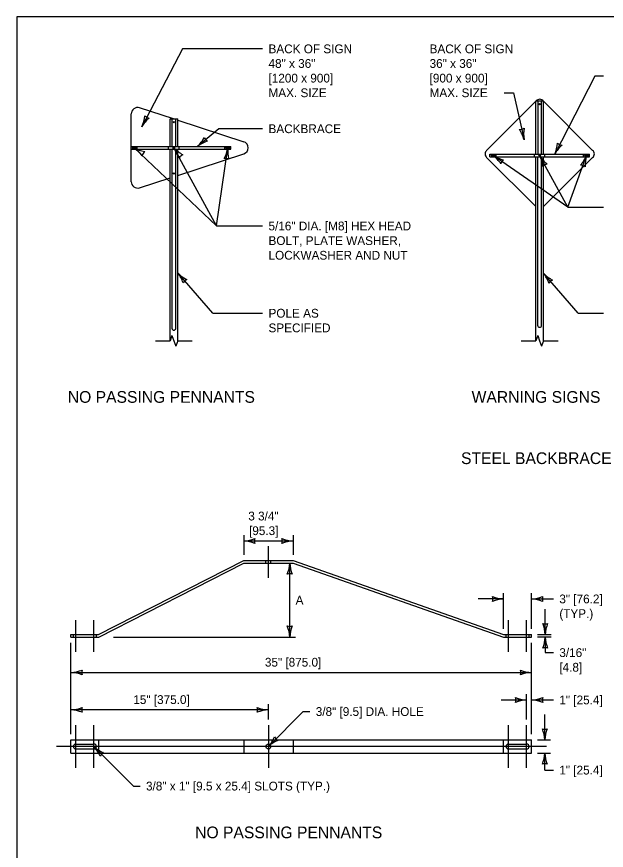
# Model space of a CAD drawing. Extents: x 49991.4 to 50021, y 49987.6 to 50011.4.
# Drawn here: x 50000.34 to 50004.36, y 50005.57 to 50011.26 of the extents above; entities that cross this region are included whole.
import ezdxf

# ---------------------------------------------------------------- set-up
doc = ezdxf.new("R2010")
doc.units = 0
for name, color, linetype in [('Level 1', 7, 'Continuous'), ('Level 2', 7, 'Continuous'), ('Level 3', 7, 'Continuous'), ('Level 4', 7, 'Continuous'), ('Level 5', 7, 'Continuous'), ('Level 6', 7, 'Continuous')]:
    doc.layers.add(name, color=color, linetype=linetype)

msp = doc.modelspace()

# ---------------------------------------------------------------- linework, layer by layer
at = {"layer": 'Level 1'}
for p, q in [((50003.8814, 50010.6855), (50003.5454, 50010.3494)), ((50003.8814, 50010.6878), (50003.9332, 50010.6878)), ((50003.8814, 50010.324), (50003.8814, 50010.6878)), ((50003.8941, 50010.6878), (50003.8941, 50010.324)), ((50003.9211, 50010.324), (50003.9211, 50010.6878)), ((50003.9332, 50010.324), (50003.9332, 50010.6878)), ((50003.9332, 50010.6855), (50004.2692, 50010.3494)), ((50001.1177, 50010.1354), (50001.1177, 50010.5983)), ((50001.406, 50010.5648), (50001.1749, 50010.6398)), ((50001.3834, 50010.5648), (50001.4352, 50010.5648)), ((50001.3834, 50010.3765), (50001.3834, 50010.5648)), ((50001.3962, 50010.5648), (50001.3962, 50010.3765)), ((50001.4232, 50010.3765), (50001.4232, 50010.5648)), ((50001.4352, 50010.3765), (50001.4352, 50010.5648)), ((50001.4352, 50010.5553), (50001.8871, 50010.4085)), ((50001.1177, 50010.3765), (50001.798, 50010.3765)), ((50001.1276, 50010.3697), (50001.149, 50010.3697)), ((50001.1276, 50010.3639), (50001.149, 50010.3639)), ((50001.159, 50010.3571), (50001.159, 50010.3765)), ((50001.3734, 50010.3571), (50001.3734, 50010.3765)), ((50001.4452, 50010.3571), (50001.4452, 50010.3765)), ((50001.7567, 50010.3571), (50001.7567, 50010.3765)), ((50001.7667, 50010.3699), (50001.7881, 50010.3699)), ((50001.7667, 50010.364), (50001.7881, 50010.364)), ((50001.798, 50010.3571), (50001.798, 50010.3765)), ((50001.1177, 50010.3571), (50001.798, 50010.3571)), ((50001.3834, 50009.0483), (50001.3834, 50010.3571)), ((50001.3958, 50010.3571), (50001.3958, 50009.1339)), ((50001.4228, 50009.1339), (50001.4228, 50010.3571)), ((50001.4352, 50009.0483), (50001.4352, 50010.3571)), ((50001.4352, 50010.1783), (50001.8872, 50010.325)), ((50003.5681, 50010.324), (50004.2485, 50010.324)), ((50003.5681, 50010.3045), (50003.5681, 50010.324)), ((50003.5681, 50010.3045), (50004.2485, 50010.3045)), ((50003.5784, 50010.3173), (50003.5998, 50010.3173)), ((50003.5784, 50010.3115), (50003.5998, 50010.3115)), ((50003.6094, 50010.3045), (50003.6094, 50010.324)), ((50003.8714, 50010.3045), (50003.8714, 50010.324)), ((50003.8814, 50009.0483), (50003.8814, 50010.3045)), ((50003.8938, 50010.3045), (50003.8938, 50009.154)), ((50003.9208, 50009.154), (50003.9208, 50010.3045)), ((50003.9332, 50009.0483), (50003.9332, 50010.3045)), ((50003.9432, 50010.3045), (50003.9432, 50010.324)), ((50004.2072, 50010.3045), (50004.2072, 50010.324)), ((50004.2173, 50010.3173), (50004.2387, 50010.3173)), ((50004.2173, 50010.3115), (50004.2387, 50010.3115)), ((50004.2485, 50010.3045), (50004.2485, 50010.324)), ((50003.8814, 50009.9648), (50003.5454, 50010.3009)), ((50003.9332, 50009.9648), (50004.2692, 50010.3009)), ((50001.1749, 50010.0938), (50001.3834, 50010.1615)), ((50000.8934, 50007.0404), (50001.8861, 50007.546)), ((50000.8971, 50007.0236), (50001.8861, 50007.5292)), ((50001.8861, 50007.546), (50002.2231, 50007.546)), ((50001.8861, 50007.5292), (50002.2231, 50007.5292)), ((50002.2231, 50007.546), (50003.6609, 50007.0404)), ((50002.2231, 50007.5292), (50003.6609, 50007.0236)), ((50000.7061, 50007.0236), (50000.7061, 50007.0404)), ((50000.7061, 50007.0404), (50000.8934, 50007.0404)), ((50000.7061, 50007.0236), (50000.8971, 50007.0236)), ((50003.6609, 50007.0404), (50003.8519, 50007.0404)), ((50003.6609, 50007.0236), (50003.8519, 50007.0236)), ((50003.8519, 50007.0236), (50003.8519, 50007.0404)), ((50000.7061, 50006.3212), (50003.8519, 50006.3212)), ((50000.7061, 50006.2314), (50000.7061, 50006.3212)), ((50000.8971, 50006.2314), (50000.8971, 50006.3212)), ((50001.8861, 50006.3212), (50001.8861, 50006.2314)), ((50002.2231, 50006.3212), (50002.2231, 50006.2314)), ((50003.6609, 50006.2314), (50003.6609, 50006.3212)), ((50003.8519, 50006.2314), (50003.8519, 50006.3212)), ((50000.7399, 50006.2932), (50000.8634, 50006.2932)), ((50003.6946, 50006.2932), (50003.8182, 50006.2932)), ((50000.7061, 50006.2314), (50003.8519, 50006.2314)), ((50000.7399, 50006.2592), (50000.8634, 50006.2592)), ((50003.6946, 50006.2592), (50003.8182, 50006.2592))]:
    msp.add_line(p, q, dxfattribs=at)
msp.add_lwpolyline([(50008.6146, 50011.2628), (50000.3356, 50011.2628), (50000.3356, 50000.0624), (50008.6146, 50000.0624)], close=True, dxfattribs=at)
for centre, radius in [((50003.9073, 50010.6648), 0.00425), ((50001.4091, 50010.5417), 0.00425), ((50001.4091, 50010.3668), 0.0051), ((50003.9073, 50010.3149), 0.0051), ((50001.4092, 50010.1919), 0.00425), ((50002.0547, 50006.2763), 0.0169)]:
    msp.add_circle(centre, radius, dxfattribs=at)
for centre, radius, start, end in [((50003.9073, 50010.6651), 0.033, 38.2128, 136.5377), ((50001.1614, 50010.5983), 0.0437, 72, 180), ((50001.1276, 50010.3668), 0.00292, 90, 270), ((50001.149, 50010.3668), 0.00292, 270, 90), ((50001.7667, 50010.367), 0.00292, 90, 270), ((50001.7881, 50010.367), 0.00292, 270, 90), ((50001.8734, 50010.3668), 0.0439, 288.2735, 71.838), ((50003.5693, 50010.3252), 0.0341, 134.5822, 225.4178), ((50003.5784, 50010.3144), 0.00292, 90, 270), ((50003.5998, 50010.3144), 0.00292, 270, 90), ((50004.2173, 50010.3144), 0.00292, 90, 270), ((50004.2387, 50010.3144), 0.00292, 270, 90), ((50004.2504, 50010.3252), 0.0307, 307.7824, 52.2176), ((50001.1614, 50010.1354), 0.0437, 180, 288), ((50001.4093, 50009.1339), 0.0135, 180, 359.8431), ((50003.9073, 50009.154), 0.0135, 180, 0), ((50000.7399, 50006.2762), 0.017, 90, 270), ((50000.8634, 50006.2762), 0.017, 270, 90), ((50003.6946, 50006.2762), 0.017, 90, 270), ((50003.8182, 50006.2762), 0.017, 270, 90)]:
    msp.add_arc(centre, radius, start, end, dxfattribs=at)
at = {"layer": 'Level 3'}
for p, q in [((50001.4689, 50011.0429), (50001.19, 50010.511)), ((50002.0156, 50011.0429), (50001.4689, 50011.0429)), ((50004.2849, 50010.8563), (50004.0104, 50010.324)), ((50004.3427, 50010.8563), (50004.2849, 50010.8563)), ((50003.6657, 50010.7429), (50003.7299, 50010.7429)), ((50003.7299, 50010.7429), (50003.8008, 50010.4223)), ((50001.7157, 50010.4971), (50001.5698, 50010.3765)), ((50002.0156, 50010.4971), (50001.7157, 50010.4971)), ((50001.7011, 50009.8326), (50001.1383, 50010.3668)), ((50001.7011, 50009.8326), (50001.4091, 50010.3668)), ((50001.7011, 50009.8326), (50001.7774, 50010.367)), ((50004.0989, 50009.962), (50003.5891, 50010.3144)), ((50004.0989, 50009.962), (50003.9073, 50010.3149)), ((50004.0989, 50009.962), (50004.228, 50010.3144)), ((50004.0989, 50009.962), (50004.3427, 50009.962)), ((50001.7011, 50009.8326), (50002.0156, 50009.8326)), ((50001.6752, 50009.2372), (50001.4352, 50009.5127)), ((50004.1708, 50009.2372), (50003.9332, 50009.5099)), ((50001.6752, 50009.2372), (50002.0156, 50009.2372)), ((50004.1708, 50009.2372), (50004.3427, 50009.2372)), ((50001.8861, 50007.7208), (50001.8861, 50007.586)), ((50002.2231, 50007.7208), (50002.2231, 50007.586)), ((50001.8861, 50007.6808), (50002.2231, 50007.6808)), ((50002.2007, 50007.0236), (50002.2007, 50007.5292)), ((50003.6609, 50007.0804), (50003.6609, 50007.3244)), ((50003.8519, 50007.0804), (50003.8519, 50007.3244)), ((50003.6609, 50007.2844), (50003.4875, 50007.2844)), ((50003.8519, 50007.2844), (50004.0019, 50007.2844)), ((50003.9453, 50007.0404), (50003.9453, 50007.2138)), ((50000.9971, 50007.0236), (50002.2407, 50007.0236)), ((50003.8919, 50007.0404), (50003.9853, 50007.0404)), ((50003.9853, 50007.0236), (50003.8919, 50007.0236)), ((50003.9453, 50007.0236), (50003.9453, 50006.9176)), ((50000.7061, 50006.3612), (50000.7061, 50006.9836)), ((50003.8521, 50006.3612), (50003.8521, 50006.9836)), ((50003.9453, 50006.9176), (50004.0019, 50006.9176)), ((50000.7061, 50006.782), (50003.8521, 50006.782)), ((50003.8182, 50006.4612), (50003.8182, 50006.6343)), ((50002.0547, 50006.4612), (50002.0547, 50006.5666)), ((50003.6448, 50006.5943), (50003.8182, 50006.5943)), ((50003.8521, 50006.5943), (50004.0019, 50006.5943)), ((50002.0547, 50006.5266), (50000.7061, 50006.5266)), ((50002.0547, 50006.2762), (50002.2933, 50006.515)), ((50002.2933, 50006.515), (50002.3383, 50006.515)), ((50003.9426, 50006.3208), (50003.9426, 50006.4942)), ((50003.8919, 50006.3208), (50003.9826, 50006.3208)), ((50001.1339, 50006.0058), (50000.8634, 50006.2762)), ((50003.8919, 50006.2314), (50003.9826, 50006.2314)), ((50003.9426, 50006.1151), (50003.9426, 50006.2314)), ((50003.9426, 50006.1151), (50004.0019, 50006.1151)), ((50001.1339, 50006.0058), (50001.1789, 50006.0058))]:
    msp.add_line(p, q, dxfattribs=at)
for centre, radius, start, end in [((50000.9784, 50010.6084), 0.233, 335.1602, 354.4101), ((50001.3823, 50010.3993), 0.2223, 129.7889, 149.9724), ((50001.2494, 50010.6241), 0.0548, 224.4717, 260.1941), ((50003.7731, 50010.5475), 0.0548, 264.6089, 300.3312), ((50003.5761, 50010.3608), 0.233, 15.2973, 34.5472), ((50004.0197, 50010.4613), 0.2223, 169.926, 190.1096), ((50001.4127, 50010.5486), 0.233, 312.3755, 331.6254), ((50001.6686, 50010.4581), 0.0548, 201.687, 237.4094), ((50001.0104, 50010.185), 0.2223, 34.9974, 55.1809), ((50001.2526, 50010.57), 0.233, 240.3687, 259.6186), ((50001.2335, 50010.2305), 0.2223, 17.6267, 37.8102), ((50001.5795, 50010.5257), 0.233, 222.998, 242.2478), ((50001.7041, 50010.1994), 0.2223, 107.0042, 127.1877), ((50001.5577, 50010.401), 0.2223, 331.0038, 351.1874), ((50002.0099, 50010.3522), 0.233, 176.3751, 195.625), ((50003.7983, 50010.4205), 0.233, 335.5438, 354.7937), ((50004.2036, 50010.214), 0.2223, 130.1725, 150.356), ((50004.0692, 50010.438), 0.0548, 224.8553, 260.5777), ((50001.2455, 50010.2987), 0.0548, 129.6802, 165.4026), ((50001.4919, 50010.2688), 0.0548, 112.3095, 148.0318), ((50003.4553, 50010.1369), 0.2223, 32.7994, 52.9829), ((50003.712, 50010.5124), 0.233, 238.1707, 257.4206), ((50003.7077, 50010.2169), 0.2223, 5.9632, 26.1467), ((50004.1063, 50010.436), 0.233, 211.3345, 230.5843), ((50004.0226, 50010.3994), 0.2223, 317.3378, 337.5213), ((50004.4505, 50010.2451), 0.233, 162.7091, 181.9589), ((50001.763, 50010.2396), 0.0548, 65.6867, 101.409), ((50003.6946, 50010.2415), 0.0548, 127.4822, 163.2046), ((50003.9685, 50010.2022), 0.0548, 100.646, 136.3684), ((50004.1839, 50010.194), 0.0548, 52.0206, 87.743), ((50001.2617, 50009.3736), 0.2223, 18.5212, 38.7047), ((50001.6031, 50009.6742), 0.233, 223.8925, 243.1424), ((50003.7597, 50009.3709), 0.2223, 18.5212, 38.7047), ((50004.1011, 50009.6714), 0.233, 223.8925, 243.1424), ((50001.5194, 50009.416), 0.0548, 113.204, 148.9264), ((50004.0174, 50009.4132), 0.0548, 113.204, 148.9264), ((50001.8746, 50007.9135), 0.233, 272.8273, 292.0772), ((50002.0143, 50007.6808), 0.0548, 162.1388, 197.8612), ((50002.2323, 50007.9029), 0.2223, 247.456, 267.6395), ((50002.0949, 50007.6808), 0.0548, 342.1388, 17.8612), ((50001.8769, 50007.4587), 0.2223, 67.456, 87.6395), ((50002.2346, 50007.4481), 0.233, 92.8273, 112.0772), ((50001.9786, 50007.5384), 0.2223, 337.456, 357.6395), ((50002.4334, 50007.5407), 0.233, 182.8273, 202.0772), ((50002.2007, 50007.401), 0.0548, 72.1388, 107.8612), ((50003.6701, 50007.5065), 0.2223, 247.456, 267.6395), ((50003.5327, 50007.2844), 0.0548, 342.1388, 17.8612), ((50003.8404, 50007.5171), 0.233, 272.8273, 292.0772), ((50003.9801, 50007.2844), 0.0548, 162.1388, 197.8612), ((50003.6724, 50007.0517), 0.233, 92.8273, 112.0772), ((50003.8427, 50007.0623), 0.2223, 67.456, 87.6395), ((50003.9453, 50007.1686), 0.0548, 252.1388, 287.8612), ((50003.7126, 50007.0289), 0.233, 2.8273, 22.0772), ((50004.1674, 50007.0312), 0.2223, 157.456, 177.6395), ((50002.2007, 50007.1518), 0.0548, 252.1388, 287.8612), ((50001.968, 50007.0121), 0.233, 2.8273, 22.0772), ((50002.4228, 50007.0144), 0.2223, 157.456, 177.6395), ((50003.7232, 50007.0328), 0.2223, 337.456, 357.6395), ((50004.178, 50007.0351), 0.233, 182.8273, 202.0772), ((50003.9453, 50006.8954), 0.0548, 72.1388, 107.8612), ((50000.6946, 50007.0147), 0.233, 272.8273, 292.0772), ((50000.6969, 50006.5599), 0.2223, 67.456, 87.6395), ((50000.8343, 50006.782), 0.0548, 162.1388, 197.8612), ((50003.8613, 50007.0041), 0.2223, 247.456, 267.6395), ((50003.7239, 50006.782), 0.0548, 342.1388, 17.8612), ((50003.8636, 50006.5493), 0.233, 92.8273, 112.0772), ((50003.8274, 50006.8164), 0.2223, 247.456, 267.6395), ((50003.69, 50006.5943), 0.0548, 342.1388, 17.8612), ((50003.8406, 50006.827), 0.233, 272.8273, 292.0772), ((50003.9803, 50006.5943), 0.0548, 162.1388, 197.8612), ((50003.8297, 50006.3616), 0.233, 92.8273, 112.0772), ((50003.8429, 50006.3722), 0.2223, 67.456, 87.6395), ((50000.6946, 50006.7593), 0.233, 272.8273, 292.0772), ((50000.6969, 50006.3045), 0.2223, 67.456, 87.6395), ((50000.8343, 50006.5266), 0.0548, 162.1388, 197.8612), ((50002.0639, 50006.7487), 0.2223, 247.456, 267.6395), ((50001.9265, 50006.5266), 0.0548, 342.1388, 17.8612), ((50002.0662, 50006.2939), 0.233, 92.8273, 112.0772), ((50003.9426, 50006.449), 0.0548, 252.1388, 287.8612), ((50003.7099, 50006.3093), 0.233, 2.8273, 22.0772), ((50004.1647, 50006.3116), 0.2223, 157.456, 177.6395), ((50001.882, 50006.4326), 0.233, 317.8513, 337.1012), ((50002.2054, 50006.1127), 0.2223, 112.48, 132.6635), ((50002.1453, 50006.3669), 0.0548, 207.1628, 242.8852), ((50000.6999, 50006.1256), 0.2223, 22.4666, 42.6501), ((50001.0198, 50006.4489), 0.233, 227.8379, 247.0878), ((50000.9541, 50006.1856), 0.0548, 117.1494, 152.8718), ((50003.7205, 50006.2406), 0.2223, 337.456, 357.6395), ((50004.1753, 50006.2429), 0.233, 182.8273, 202.0772), ((50003.9426, 50006.1032), 0.0548, 72.1388, 107.8612)]:
    msp.add_arc(centre, radius, start, end, dxfattribs=at)
at = {"layer": 'Level 4'}
for p, q in [((50002.0378, 50007.5292), (50002.0378, 50007.546)), ((50002.0715, 50007.5292), (50002.0715, 50007.546)), ((50000.7229, 50007.0236), (50000.7229, 50007.0404)), ((50000.8804, 50007.0236), (50000.8804, 50007.0404)), ((50003.6777, 50007.0236), (50003.6777, 50007.0404)), ((50003.8351, 50007.0236), (50003.8351, 50007.0404))]:
    msp.add_line(p, q, dxfattribs=at)
at = {"layer": 'Level 5'}
for p, q in [((50002.0547, 50007.4292), (50002.0547, 50007.646)), ((50000.7399, 50006.9236), (50000.7399, 50007.1404)), ((50000.8634, 50006.9236), (50000.8634, 50007.1404)), ((50003.6946, 50006.9236), (50003.6946, 50007.1404)), ((50003.8182, 50006.9236), (50003.8182, 50007.1404)), ((50000.7399, 50006.1314), (50000.7399, 50006.4212)), ((50000.8634, 50006.1314), (50000.8634, 50006.4212)), ((50002.0547, 50006.4212), (50002.0547, 50006.1314)), ((50003.6946, 50006.1314), (50003.6946, 50006.4212)), ((50003.8182, 50006.1314), (50003.8182, 50006.4212)), ((50003.9544, 50006.2762), (50000.6086, 50006.2762))]:
    msp.add_line(p, q, dxfattribs=at)
at = {"layer": 'Level 6'}
for p, q in [((50001.3963, 50009.0849), (50001.3834, 50009.0483)), ((50001.3963, 50009.0849), (50001.4093, 50009.0483)), ((50003.8943, 50009.0849), (50003.8814, 50009.0483)), ((50003.8943, 50009.0849), (50003.9073, 50009.0483)), ((50001.2834, 50009.0483), (50001.3834, 50009.0483)), ((50001.4093, 50009.0483), (50001.4223, 50009.0117)), ((50001.4352, 50009.0483), (50001.4223, 50009.0117)), ((50001.4352, 50009.0483), (50001.5352, 50009.0483)), ((50003.7814, 50009.0483), (50003.8814, 50009.0483)), ((50003.9073, 50009.0483), (50003.9203, 50009.0117)), ((50003.9332, 50009.0483), (50003.9203, 50009.0117)), ((50003.9332, 50009.0483), (50004.0332, 50009.0483))]:
    msp.add_line(p, q, dxfattribs=at)

# ---------------------------------------------------------------- texts
at = {"layer": 'Level 2'}
for s, height, p in [('BACK OF SIGN', 0.06, (50002.0556, 50011.0129)), ('BACK OF SIGN', 0.06, (50003.1557, 50011.0129)), ('48" x 36"', 0.06, (50002.0556, 50010.9129)), ('36" x 36"', 0.06, (50003.1557, 50010.9129)), ('[1200 x 900]', 0.06, (50002.0556, 50010.8129)), ('[900 x 900]', 0.06, (50003.1557, 50010.8129)), ('MAX. SIZE', 0.06, (50002.0556, 50010.7129)), ('MAX. SIZE', 0.06, (50003.1557, 50010.7129)), ('BACKBRACE', 0.06, (50002.0556, 50010.4671)), ('5/16" DIA. [M8] HEX HEAD', 0.06, (50002.0556, 50009.8026)), ('BOLT, PLATE WASHER, ', 0.06, (50002.0556, 50009.7026)), ('LOCKWASHER AND NUT', 0.06, (50002.0556, 50009.6026)), ('POLE AS', 0.06, (50002.0556, 50009.2065)), ('SPECIFIED', 0.06, (50002.0556, 50009.1065)), ('NO PASSING PENNANTS', 0.08, (50000.6848, 50008.6246)), ('WARNING SIGNS', 0.08, (50003.4428, 50008.6246)), ('STEEL BACKBRACE INSTALLATIONS', 0.08, (50003.3705, 50008.206)), ('3 3/4"', 0.06, (50001.9175, 50007.8208)), ('[95.3]', 0.06, (50001.9226, 50007.7208)), ('A', 0.06, (50002.2407, 50007.2464)), ('3" [76.2]', 0.06, (50004.0419, 50007.2544)), ('(TYP.)', 0.06, (50004.0419, 50007.1544)), ('3/16"', 0.06, (50004.0419, 50006.8876)), ('35" [875.0]', 0.06, (50002.0309, 50006.822)), ('[4.8]', 0.06, (50004.0419, 50006.7876)), ('15" [375.0]', 0.06, (50001.1323, 50006.5666)), ('1" [25.4]', 0.06, (50004.0419, 50006.5643)), ('3/8" [9.5] DIA. HOLE', 0.06, (50002.3783, 50006.485)), ('1" [25.4]', 0.06, (50004.0419, 50006.0851)), ('3/8" x 1" [9.5 x 25.4] SLOTS (TYP.)', 0.06, (50001.2189, 50005.9758)), ('NO PASSING PENNANTS', 0.08, (50001.5545, 50005.6494))]:
    msp.add_text(s, height=height, dxfattribs=at).set_placement(p)

doc.saveas('drawing.dxf')
